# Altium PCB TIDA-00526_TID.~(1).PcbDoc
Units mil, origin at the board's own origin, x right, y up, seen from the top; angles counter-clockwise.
Board outline 2000 x 2000 mil, 2 copper layers (Top Layer, Bottom Layer), stack 62 mil thick; 38 components, 13 nets, 59 pads, 2 vias.
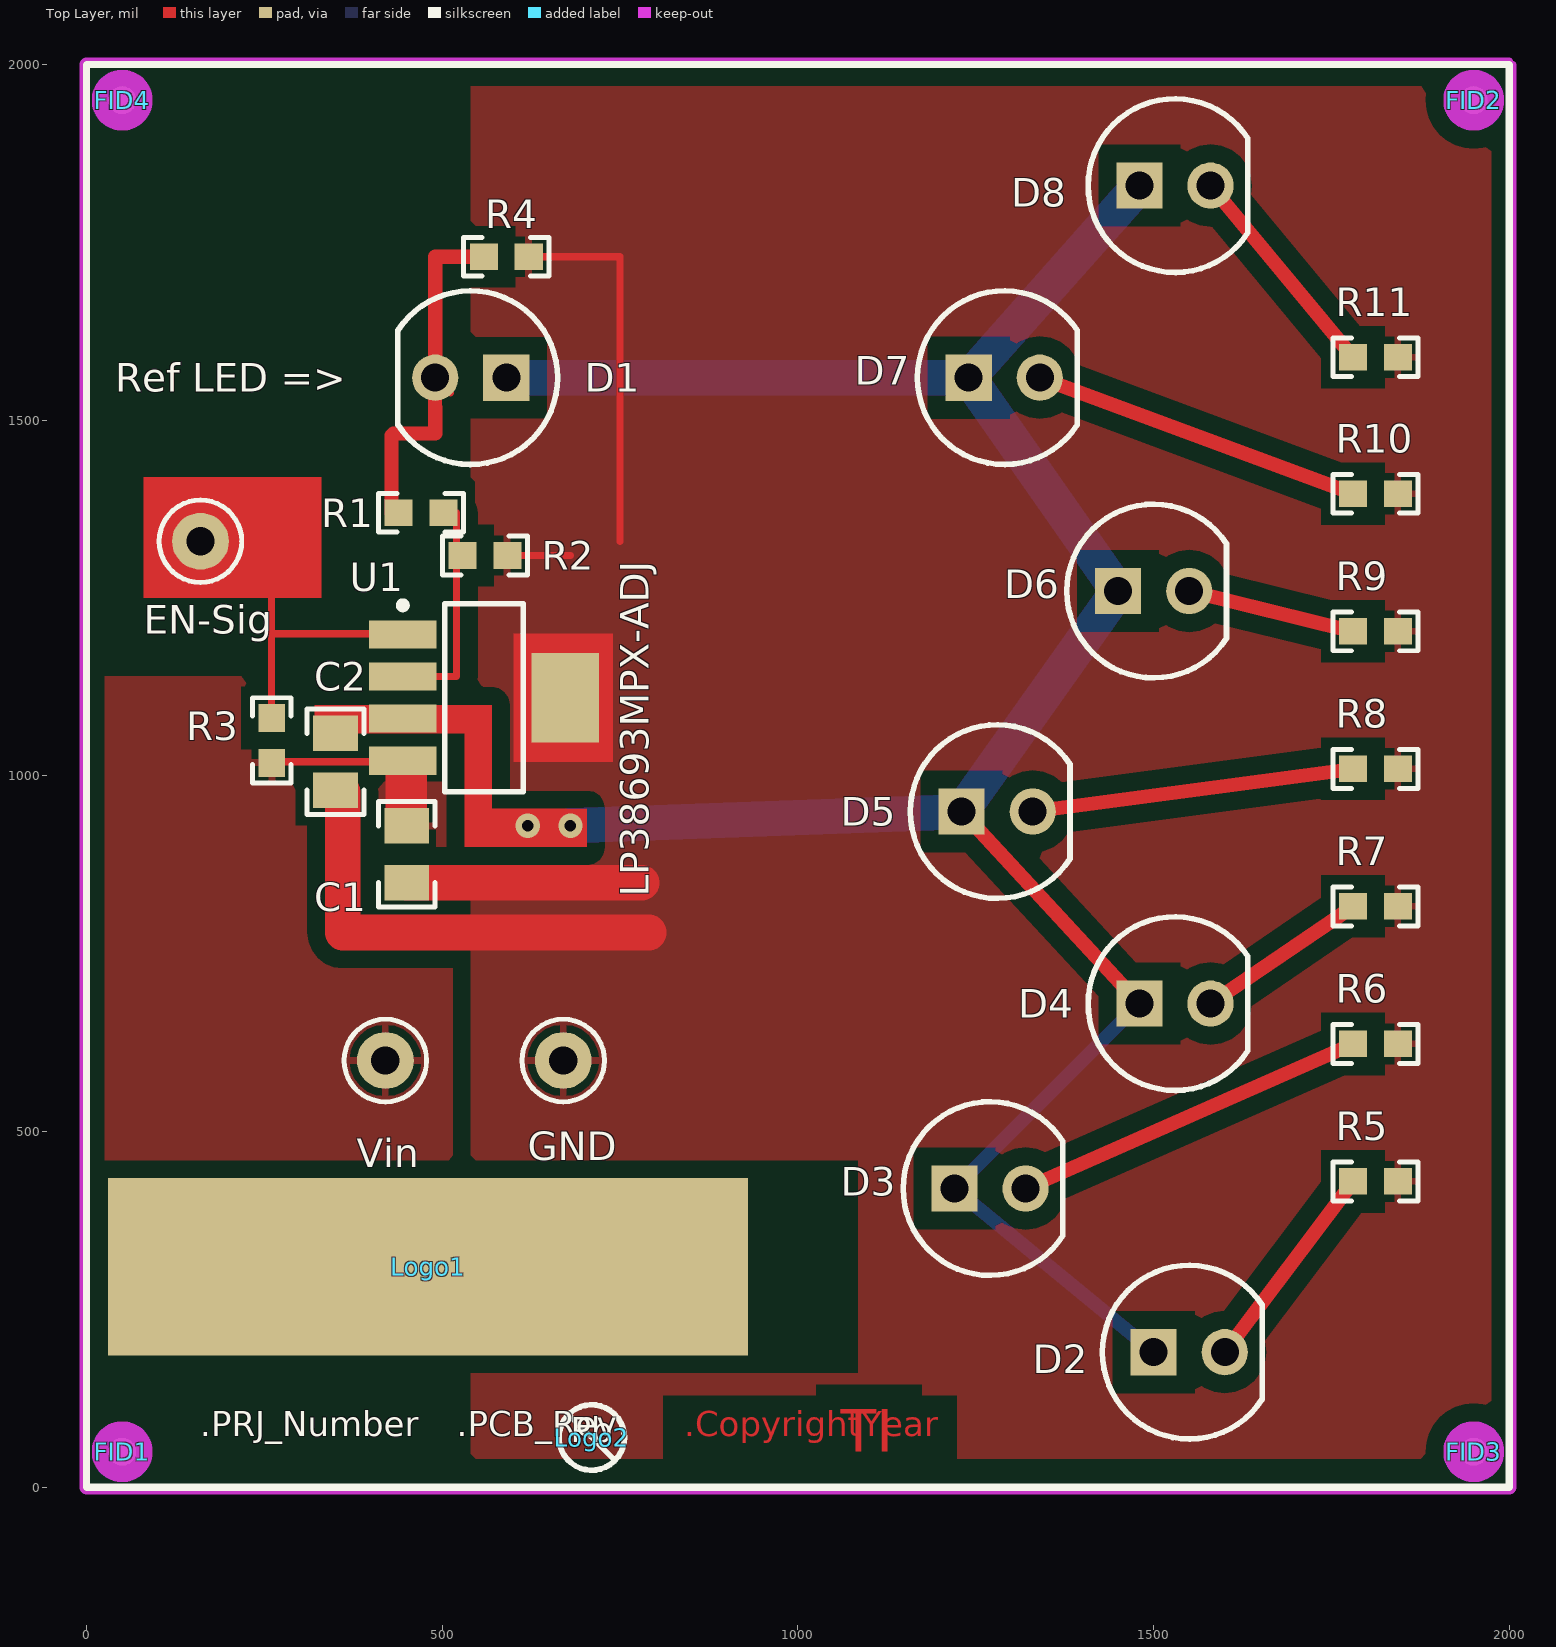
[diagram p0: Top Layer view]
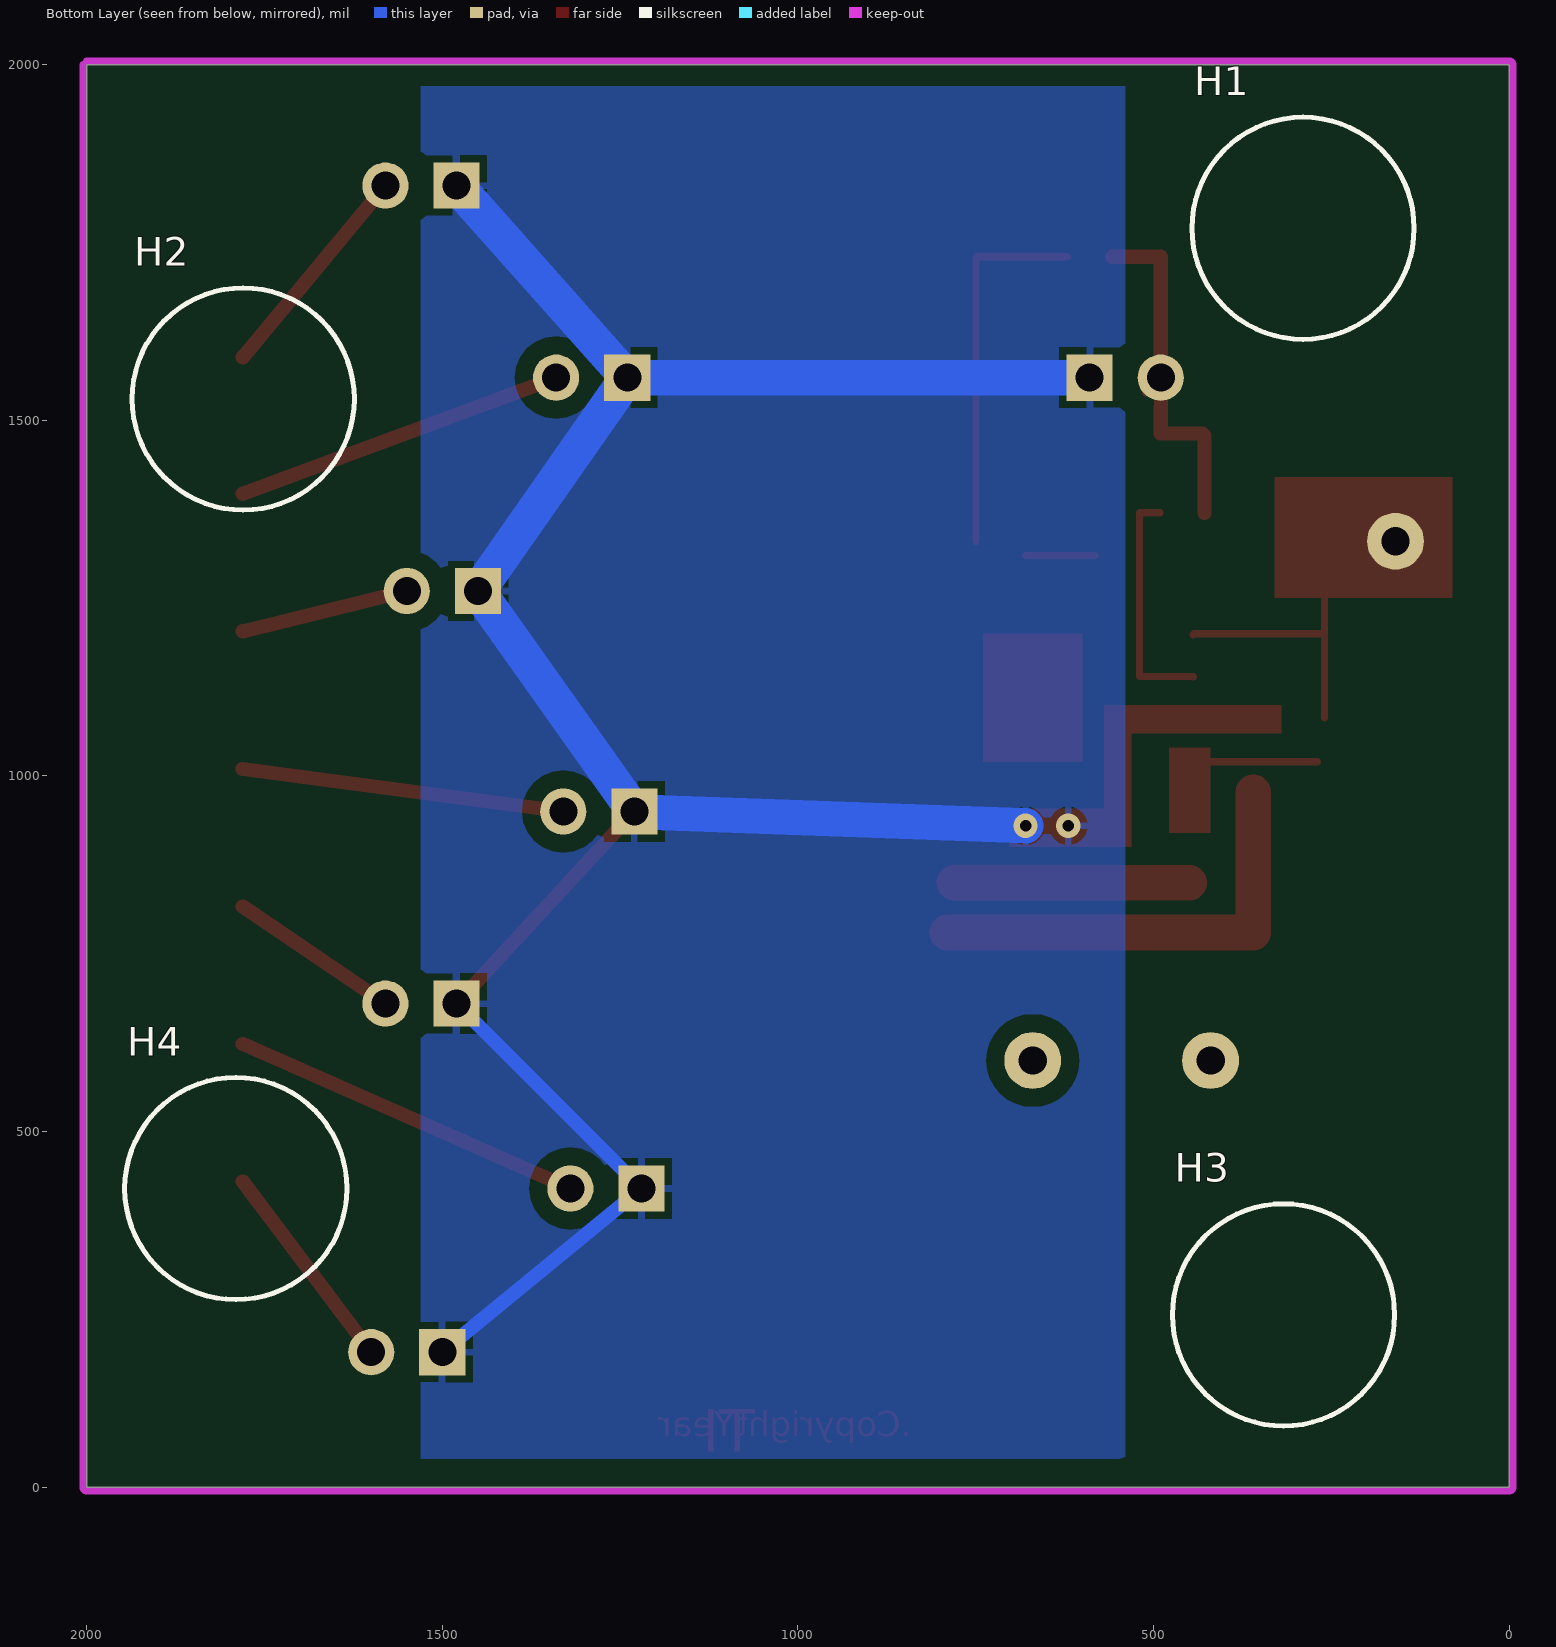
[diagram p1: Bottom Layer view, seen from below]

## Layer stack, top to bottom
Top Solder: solder mask 0.4, Solder Resist, Dk 3.5
Top Layer: signal copper 1.4
Dielectric1: core 59.2, FR-4, Dk 4.8
Bottom Layer: signal copper 1.4
Bottom Solder: solder mask 0.4, Solder Resist, Dk 3.5

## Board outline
0,0 2000,0 2000,2000 0,2000

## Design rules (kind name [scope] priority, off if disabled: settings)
AcuteAngle [All] p1: minimum=4.50000000000000E+0001 checktracksonly=FALSE
AssemblyTestPointUsage [All] p1: valid=2
Clearance Clearance_Keepouts [((IsTrack Or IsArc) And Not InPoly) And IsFree and IsKeepOut vs ((IsTrack Or IsArc) And Not InPoly) And IsFree and IsKeepOut] p1: gap=0
Clearance Clearance_BoardEdge_MountingHoles [OnCopper and InComponentClass('Mounting Holes') vs IsKeepOut] p2: gap=40
Clearance Clearance_BoardEdge_Poly [OnCopper and InPoly vs IsKeepOut] p3: gap=25
Clearance Clearance_BoardEdge [OnCopper and Not InComponentClass('Logo') and not InComponentClass('FiducialMark') and not InRegion(1000,500,4000,800) and Not IsKeepout vs IsKeepOut] p4: gap=75
Clearance Clearance_Poly [InPolygon] p5: gap=25
Clearance [All] p6: gap=7.87
ComponentClearance ComponentClearance_MountingHoles_FiducialMarks [InComponentClass('Mounting Holes') vs InComponentClass('FiducialMark')] p1: gap=50 collisioncheckmode=3 verticalgap=10 showdistances=FALSE
ComponentClearance ComponentClearance_Shunt [InComponentClass('Header') vs InComponentClass('Shunt')] p2: gap=0 collisioncheckmode=3 verticalgap=0 showdistances=FALSE
ComponentClearance ComponentClearance_Logo [InComponentClass('Logo')] p3: gap=50 collisioncheckmode=3 verticalgap=10 showdistances=FALSE
ComponentClearance ComponentClearance_ScrewToNut [(HasFootprint('NY PMS 440 0025 PH')) vs (HasFootprint('Keystone_1902C'))] p4: gap=5 collisioncheckmode=3 verticalgap=10 showdistances=FALSE
ComponentClearance ComponentClearance_MountingHoles [InComponentClass('Mounting Holes')] p5: gap=250 collisioncheckmode=3 verticalgap=100000 showdistances=FALSE
ComponentClearance ComponentClearance_SmallPassives [HasFootprint('0201*') or HasFootprint('0402*') or HasFootprint('0508') or HasFootprint('0603*') or HasFootprint('0612') or HasFootprint('0805*') or HasFootprint('0815*') or HasFootprint('0830*') or HasFootprint('1206*') or HasFootprint('1210*') or HasFootprint('1808*') or HasFootprint('1812*') or HasFootprint('1825*') or HasFootprint('2010*') or HasFootprint('2220*') or HasFootprint('2225*') or HasFootprint('2512*') or HasFootprint('2728*') or HasFootprint('3518*') vs HasFootprint('0201*') or HasFootprint('0402*') or HasFootprint('0508') or HasFootprint('0603*') or HasFootprint('0612') or HasFootprint('0805*') or HasFootprint('0815*') or HasFootprint('0830*') or HasFootprint('1206*') or HasFootprint('1210*') or HasFootprint('1808*') or HasFootprint('1812*') or HasFootprint('1825*') or HasFootprint('2010*') or HasFootprint('2220*') or HasFootprint('2225*') or HasFootprint('2512*') or HasFootprint('2728*') or HasFootprint('3518*')] p6: gap=20 collisioncheckmode=3 verticalgap=10 showdistances=FALSE
ComponentClearance ComponentClearance_THtoSMT [IsThruComponent vs IsSMTComponent] p7: gap=100 collisioncheckmode=3 verticalgap=30 showdistances=FALSE
ComponentClearance ComponentClearance_THtoTH [IsThruComponent vs IsThruComponent] p8: gap=118.11 collisioncheckmode=3 verticalgap=30 showdistances=FALSE
ComponentClearance [All] p9: gap=40 collisioncheckmode=3 verticalgap=10 showdistances=FALSE
DiffPairsRouting [All] p1: maxlimit=100 minlimit=10 mostfreqgap=10 toplayer_minwidth=15 toplayer_maxwidth=15 toplayer_prefwidth=15 bottomlayer_minwidth=15 bottomlayer_maxwidth=15 bottomlayer_prefwidth=15 maxuncoupledlength=1000
FabricationTestPointUsage TestPointUsage [All] p1: valid=2 allowmultiple=FALSE
FabricationTestpoint Testpoint [All] p1: side=3 testpointundercomponent=TRUE minsize=40 maxsize=100 preferedsize=60 minholesize=0 maxholesize=40 preferedholesize=32 testpointgrid=1 allowsidetop=TRUE allowsidebottom=TRUE usegrid=TRUE gridtolerance=0.01
FanoutControl Fanout_LCC [IsLCC] p1: bgadir=Out bgaviamode=Centered fanoutstyle=Auto fanoutdirection=Alternating viagrid=1 // Fanout_LCC (Default Rule)
FanoutControl Fanout_BGA [IsBGA] p2: bgadir=Out bgaviamode=Centered fanoutstyle=Auto fanoutdirection=Alternating viagrid=1 // Fanout_BGA (Default Rule)
FanoutControl Fanout_Default [All] p4: bgadir=Out bgaviamode=Centered fanoutstyle=Auto fanoutdirection=Alternating viagrid=1 // Fanout_Default (Default Rule)
FanoutControl Fanout_Small [(CompPinCount < 5)] p5: bgadir=Out bgaviamode=Centered fanoutstyle=Auto fanoutdirection=OutThenIn viagrid=1 // Fanout_Small (Default Rule)
HoleSize [All] p1: absolutevalues=TRUE maxlimit=251 minlimit=8 maxpercent=80.000 minpercent=20.000
MinimumAnnularRing MinimumAnnularRing_ThermalPadVias [IsVia and InAnyComponent] p1: minimumring=5.91
MinimumAnnularRing [All] p2: minimumring=9
MinimumSolderMaskSliver MinimumSolderMaskSliver_Logo [InComponentClass('Logo') vs InComponentClass('Logo')] p1: minsoldermaskwidth=0.7
MinimumSolderMaskSliver [All] p2: minsoldermaskwidth=3.94
PlaneConnect [All] p1: planeconnectstyle=Relief reliefexpansion=10 reliefentries=4 reliefconductorwidth=10 reliefairgap=10
PolygonConnect [All] p1: connectstyle=Relief reliefconductorwidth=10 reliefentries=4 polygonreliefangle="90 Angle" airgapwidth=10
RoutingVias ThermalPadVias [IsVia and InAnyComponent] p1: holewidth=7.87 width=19.68 viastyle="Through Hole" minholewidth=7.87 minwidth=19.68 maxholewidth=12.99 maxwidth=23.62
RoutingVias [All] p2: holewidth=16 width=34 viastyle="Through Hole" minholewidth=7.87 minwidth=26 maxholewidth=40 maxwidth=65
SilkToBoardRegionClearance [Not ((IsComment or IsDesignator) And (Hide <> 'False')) and not InRegion(1000,500,4000,800)] p1:
SilkToSilkClearance SilkToSilkClearance_Pb-FreeLogo [(HasFootprint('Pb-Free_Overlay_Medium') OR HasFootprint('Pb-Free_Overlay_Small')) vs (HasFootprint('Pb-Free_Overlay_Medium') OR HasFootprint('Pb-Free_Overlay_Small'))] p1: silktosilkclearance=0
SilkToSilkClearance [All] p2: silktosilkclearance=5
SilkToSolderMaskClearance "Silk to Solder Mask Opening" [All] p1: minsilkscreentomaskgap=1 clearancetoexposedcopper=FALSE
SolderMaskExpansion [All] p1: expansion=1.97
UnpouredPolygon [All] p1: allowunpoured=FALSE
Width [All] p1: maxlimit=100 minlimit=6 preferedwidth=10 checkconnectedcopper=TRUE
14 further rules are at their usual default settings.

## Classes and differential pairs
component class Logo: Logo1
component class TIDA-00526_Hardware: FID1 FID2 FID3 FID4 H1 H2 H3 H4 Logo1 Logo2 ZZ2 ZZ3 ZZ4
component class FiducialMark: FID1 FID2 FID3 FID4
component class AssemblyNote: ZZ2 ZZ3 ZZ4
component class TIDA-00526_BlankSheet: C1 C2 D1 D2 D3 D4 D5 D6 D7 D8 D? EN-Sig GND R1 R2 R3 R4 R5 R6 R7 R8 R9 R10 R11 U1 Vin

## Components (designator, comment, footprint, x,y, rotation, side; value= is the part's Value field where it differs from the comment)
C1 "C0805C104K3RACTU" 0805_HV 450,890 r90 top
C2 "C0805C104K3RACTU" 0805_HV 350,1020 r90 top
D1 "C503D-WAN-CCBDB232" HLMP-341_YELLOW 540,1560 r180 top
D2 "C503D-WAN-CCBDB232" HLMP-341_YELLOW 1550,190 r0 top
D3 "LED, White, TH" HLMP-341_YELLOW 1270,420 r0 top
D4 "C503D-WAN-CCBDB232" HLMP-341_YELLOW 1530,680 r0 top
D5 "C503D-WAN-CCBDB232" HLMP-341_YELLOW 1280,950 r0 top
D6 "C503D-WAN-CCBDB232" HLMP-341_YELLOW 1500,1260 r0 top
D7 "C503D-WAN-CCBDB232" HLMP-341_YELLOW 1290,1560 r0 top
D8 "C503D-WAN-CCBDB232" HLMP-341_YELLOW 1530,1830 r0 top
EN-Sig "5002" Keystone5002 160,1330 r0 top
FID1 "Fiducial" Fiducial10-20 50,50 r0 top
FID2 "Fiducial" Fiducial10-20 1950,1950 r0 top
FID3 "Fiducial" Fiducial10-20 1950,50 r0 top
FID4 "Fiducial" Fiducial10-20 50,1950 r0 top
GND "5001" Keystone5001 670,600 r0 top
H1 "SJ61A1" Bumpon_SJ61A1 290,1770 r180 bottom
H2 "SJ61A1" Bumpon_SJ61A1 1780,1530 r180 bottom
H3 "SJ61A1" Bumpon_SJ61A1 317.38,242.36 r180 bottom
H4 "SJ61A1" Bumpon_SJ61A1 1790.3,420 r180 bottom
Logo1 "Texas Instruments" TI_Stacked_SolderMask_Small 480,310 r0 top
Logo2 "Pb-Free Symbol" Pb-Free_Overlay_Small 710,70 r0 top
R1 "CRCW06032K32FKEA" 0603 470,1370 r180 top
R2 "RC0603FR-0712KL" 0603 560,1310 r180 top
R3 "CRCW060310K0FKEA" 0603 260,1050 r270 top
R4 "CRCW0603102RFKEA" 0603 590,1730 r180 top
R5 "CRCW0603102RFKEA" 0603 1811.95,430 r180 top
R6 "CRCW0603102RFKEA" 0603 1811.95,623.33 r180 top
R7 "CRCW0603102RFKEA" 0603 1811.95,816.67 r180 top
R8 "CRCW0603102RFKEA" 0603 1811.95,1010 r180 top
R9 "CRCW0603102RFKEA" 0603 1811.95,1203.33 r180 top
R10 "CRCW0603102RFKEA" 0603 1811.95,1396.67 r180 top
R11 "CRCW0603102RFKEA" 0603 1811.95,1588.7 r180 top
U1 "LP38693MP-ADJ" MP05A_N 558.54,1110 r0 top
Vin "5000" Keystone5000 420,600 r0 top (schematic designator VCC)
ZZ2 "These assemblies are ESD sensitive, ESD precautions shall be observed." AssemblyNote 185,3829.11 r0 top
ZZ3 "These assemblies must be clean and free from flux and all contaminants. Use of no clean flux is not acceptable." AssemblyNote 185,3740.56 r0 top
ZZ4 "These assemblies must comply with workmanship standards IPC-A-610 Class 2, unless otherwise specified." AssemblyNote 185,3652 r0 top

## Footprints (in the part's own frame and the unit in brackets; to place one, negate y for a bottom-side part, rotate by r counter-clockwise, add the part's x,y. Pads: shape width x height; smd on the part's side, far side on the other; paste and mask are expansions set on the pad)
0603 [mm] "0603 from SM-752 data"
  rect 1x0.95 smd: 1(-0.8,0) 2(0.8,0)
  silkscreen extent -1.52,-0.69 1.52,0.69, body extent -0.87,-0.47 0.87,0.47, height 0.85
0805_HV [mil] "0805 with 30mil clearance between pads"
  rect 50x63 smd: 1(-40,0) 2(40,0)
  silkscreen extent -74,-40 74,40, body extent -43,-29 43,29, height 43
AssemblyNote [mil] "Assembly Note"
Bumpon_SJ61A1 [mil] "3M Cylindrical Bumpon black"
  round 1 on Mech4: 0(0,0)
  silkscreen extent -156,-156 156,156, body extent -156,-155 156,156, height 201
Fiducial10-20 [mm]
  round 1 smd mask+0.5: 1(0,0)
  Top Layer keep-out circle w1.178: c0,0 r0.5
HLMP-341_YELLOW [mm] "AVAGO"
  rect 1.65x1.65 hole 1: 1(-1.27,0)
  round 1.65 hole 1: 2(1.27,0)
  silkscreen extent -3.1,-3.1 2.6,3.1, body extent -3.06,-3.06 2.58,3.06, height 10.78
Keystone5000 [mil] "For Keystone 500x miniature loop terminals"
  round 80 hole 40: 1(0,0)
  silkscreen extent -58,-58 58,58, body extent -49,-49 49,49, height 182
Keystone5001 [mil] "For Keystone 500x miniature loop terminals"
  round 80 hole 40: 1(0,0)
  silkscreen extent -58,-58 58,58, body extent -49,-49 49,49, height 182
Keystone5002 [mil] "For Keystone 500x miniature loop terminals"
  round 80 hole 40: 1(0,0)
  silkscreen extent -58,-58 58,58, body extent -49,-49 49,49, height 182
MP05A_N [mm] "SOT223, 5-Leads, Body 6.5x3.5mm, Pitch 1.5mm, Lead Span 7mm, IPC Medium Density"
  rect 2.4x1 smd: 1(-2.9,2.25) 2(-2.9,0.75) 3(-2.9,-0.75) 4(-2.9,-2.25)
  rect 2.4x3.2 smd: 5(2.9,0)
  silkscreen extent -3.02,-3.35 1.4,3.42, body extent -1.85,-3.35 1.85,3.35, height 1.8
Pb-Free_Overlay_Small [mil]
  silkscreen extent -46,-46 46,46
TI_Stacked_SolderMask_Small [mil]
  rect 900x250 smd paste-125 mask-125: 0(0,0)

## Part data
C1 C2: "CAP, CERM, 0.1 µF, 25 V, +/- 10%, X7R, 0805"
D1 D2 D4 D5 D7 D8: library part HLMP-3416, "LED, White, TH"
D3: library part HLMP-3416
D6: library part HLMP-3416, "LED, white, TH"
EN-Sig: "Test Point, Miniature, White, TH"
FID1 FID2 FID3 FID4: "Fiducial mark.  There is nothing to buy or mount."
GND: "Test Point, Miniature, Black, TH"
H1 H2 H3 H4: "Bumpon, Cylindrical, 0.312 X 0.200, Black"
Logo1: library part TI_Logo, "Texas Instrument Corporate Signature"
Logo2: library part Pb-Free
R1: "RES, 2.32 k, 1%, 0.1 W, 0603"
R2: "RES, 12.0 k, 1%, 0.1 W, 0603"
R3: "RES, 10.0 k, 1%, 0.1 W, 0603"
R4 R5 R6 R7 R8 R9 R10 R11: "RES, 102, 1%, 0.1 W, 0603"
U1: "500mA Low Dropout CMOS Linear Regulators, 5-pin SOT-223"
Vin: "Test Point, Miniature, Red, TH"
ZZ2 ZZ3 ZZ4: library part AssemblyNote

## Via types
v1: diameter 34, hole 16, Top Layer to Bottom Layer, 2 vias

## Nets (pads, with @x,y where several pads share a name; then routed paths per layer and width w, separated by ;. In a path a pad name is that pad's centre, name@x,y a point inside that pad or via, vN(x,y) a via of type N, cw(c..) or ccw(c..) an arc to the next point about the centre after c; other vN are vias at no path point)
GND: C1.1 C2.1 GND.1 R2.1 R4.1 R5.1 R6.1 R7.1 R8.1 R9.1 R10.1 R11.1 U1.5 | length 1588.3
  Top Layer w10: C2.1 C2.1@353.05,976.95 ; R2.1@581.5,1310 680,1310 ; R4.1 750,1730 750,1330
  Top Layer w50: C2.1@360,976.95 360,780 790,780 ; C1.1 780,850
NetC1_2: C1.2 R3.2 U1.4 Vin.1 | length 173
  Top Layer w10: R3.2@270,1020 U1.4@442.95,1020
NetD1_2: D1.2 R1.2 R4.2 | length 510.4
  Top Layer w10: D1.2@510,1540 D1.2@511.5,1538.5
  Top Layer w20: R1.2@428.5,1370 428.5,1478.5 431.5,1481.5 490,1481.5 D1.2@489.8,1560 ; D1.2@490,1540 490,1730 R4.2
NetD2_2: D2.2 R5.2 | length 300.3
  Top Layer w20: D2.2 R5.2
NetD3_2: D3.2 R6.2 | length 503.4
  Top Layer w20: D3.2 R6.2
NetD4_2: D4.2 R7.2 | length 242.6
  Top Layer w20: D4.2 R7.2
NetD5_2: D5.2 R8.2 | length 454.4
  Top Layer w20: D5.2 R8.2
NetD6_2: D6.2 R9.2 | length 237.3
  Top Layer w20: D6.2 R9.2
NetD7_2: D7.2 R10.2 | length 469.8
  Top Layer w20: D7.2 R10.2
NetD8_2: D8.2 R11.2 | length 313.7
  Top Layer w20: D8.2 R11.2
NetEN-Sig_1: EN-Sig.1 R3.1 U1.1 | length 520.4
  Top Layer w10: EN-Sig.1 221.5,1268.5 ; R3.1 260,1200 ; 260,1330 260,1200 ; U1.1 442.95,1200 260,1200
NetR1_1: R1.1 R2.2 U1.2 | length 334.1
  Top Layer w10: U1.2 520,1140 520,1370 R1.1 R1.1@491.5,1370
VOUT: C2.2 D1.1 D2.1 D3.1 D4.1 D5.1 D6.1 D7.1 D8.1 U1.3 | length 3464.2
  Top Layer w10: 650,930 v1(680,930)
  Top Layer w20: D5.1 D4.1
  Bottom Layer w10: D5.1@1210,930 D5.1
  Bottom Layer w20: D4.1 D3.1 D2.1
  Bottom Layer w50: D1.1 D7.1 ; v1(680,930) D5.1 D6.1 D7.1 ; D8.1 D7.1
  other v1: 620,930
pads on no net: FID1.1 FID2.1 FID3.1 FID4.1 H1.0 H2.0 H3.0 H4.0 Logo1.0

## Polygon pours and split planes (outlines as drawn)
NetC1_2 on Top Layer "Top Layer-No Net 2" (solid, remove dead copper, pour order 9): 20,1140 600,1140 600,400 20,400
GND on Top Layer "Top Layer-No Net 1" (solid, remove dead copper, pour order 7): 540,1970 540,40 1980,40 1980,1970
VOUT on Top Layer "Top Layer-No Net" (solid, remove dead copper, shelved, pour order 2): 0,0 0,2000 2000,2000 2000,0
VOUT on Bottom Layer "Bottom Layer-No Net" (solid, remove dead copper, pour order 12): 540,1970 1530,1970 1530,40 550,40 540,30

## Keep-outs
Keep-Out Layer:
  lines w10: 2000,2005 0,2005 ccw(c0,2000) -5,2000 -5,0 ccw(c0,0) 0,-5 2000,-5 ccw(c2000,0) 2005,0 2005,2000 ; 4950,-5 ccw(c4950,0) 4955,0 cw(c4950,0) 4950,-5 ; 4950,3455 cw(c4950,3450) 4955,3450 ccw(c4950,3450) 4950,3455
  text ".Layer_Name" at 577,-858.49 h60

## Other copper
Top Layer:
  rectangle net GND: 600,1020 740,1200
  rectangle net NetEN-Sig_1: 80,1250 330,1420
  rectangle net VOUT: 531.3,900 570,1088.35
  rectangle net VOUT: 418.54,1060 570,1100
  rectangle net VOUT: 560,900 703.65,954.02
  rectangle net VOUT: 320,1060 418.54,1100
  rectangle net NetC1_2: 420,920 478.54,1040
  text ".CopyrightYear" at 840,60 h60
  text "TI" at 1060,50 h60
  text ".Layer_Name" at 577,-858.49 h60
Bottom Layer:
  text ".Layer_Name" at 577,-858.49 h60

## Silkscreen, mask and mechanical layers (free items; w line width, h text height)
Top Overlay:
  the board outline again, w10
  text "Ref LED =>" at 40,1540 h40
  text "LP38693MPX-ADJ" at 790,830 h40 r90
  text ".PRJ_Number" at 160,60 h60
  text ".PCB_Rev" at 520,60 h60
  text ".Layer_Name" at 577,-858.49 h60
Bottom Overlay:
  text ".Layer_Name" at 577,-858.49 h60
Top Paste:
  text ".Layer_Name" at 577,-858.49 h60
Bottom Paste:
  text ".Layer_Name" at 577,-858.49 h60
Top Solder:
  the board outline again, w10
  text ".Layer_Name" at 577,-858.49 h60
  text ".Layer_Name" at 577,-858.49 h60
Bottom Solder:
  lines w10: 0,0 2000,0 ; 0,0 0,2000 ; 0,0 2000,0 ; 0,0 0,2000 ; 0,2000 2000,2000 ; 0,2000 2000,2000 ; 2000,0 2000,2000 ; 2000,0 2000,2000
  text ".Layer_Name" at 577,-858.49 h60
Drill Guide:
  text ".Layer_Name" at 577,-858.49 h60
M1 Board Outline:
  the board outline again, w10
  text ".Layer_Name" at 577,-858.49 h60
M2 Board Dimensions:
  rectangle: 0,-275 125,-150
  rectangle: 125,-400 500,-275
  lines w7: 0,-275 1000,-275 ; 125,-400 125,-150 ; 250,-400 250,-150 ; 500,-400 500,-150 ; 750,-400 750,-150 ; 0,-400 1000,-400 1000,-150 0,-150 0,-400
  text ".Layer_Name" at 577,-858.49 h60
M3 3D STEP Top:
  text ".Layer_Name" at 577,-858.49 h60
M4 3D STEP Bottom:
  text ".Layer_Name" at 577,-858.49 h60
M5 Assembly Top:
  lines w10: -292,-930.17 6308,-930.17 ; -292,-726.83 6310,-726.83 ; -292,-523.5 -292,-1133.5 3713,-1133.5 6310,-1133.5 6310,-523.5 -291.5,-523.5 -291.5,-1133.5 1284,-1133.5 ; 2173,-1133.5 2173,-523.5 ; 3440,-726.83 3440,-523.5 ; 4280,-726.83 4280,-523.5 ; 4902,-1140 4902,-937.17
  text "COMPONENTS MARKED 'DNP' SHOULD NOT BE POPULATED." at 1153.5,-318.5 h60
  text "ASSEMBLY VARIANT:" at 1153,-434 h60
  text ".VariantName" at 2189,-434 h60
  text "PCB VIEWED FROM TOP SIDE" at -228.5,-655.67 h60
  text "BOARD #:" at 2248,-655.67 h60
  text ".PRJ_Number" at 2793.5,-655.67 h60
  text "REV:" at 3638,-655.67 h60
  text ".PCB_Rev" at 3929.5,-655.67 h60
  text "SVN REV:" at 4476,-655.67 h60
  text ".VersionControl_RevNumber" at 4982,-655.67 h60
  text "PLOT NAME =" at -228.5,-1064.34 h60
  text ".plot_File_Name" at 577,-1064.34 h60
  text "GENERATED    :" at 2250,-1064.34 h60
  text ".Print_Date" at 3119.5,-1064.34 h60
  text ".Print_Time" at 3848.5,-1064.34 h60
  text "TEXAS INSTRUMENTS" at 5113,-1064.34 h60
M6 Assembly Bottom:
  lines w10: -292.5,-727.33 6309.5,-727.33 ; -290.5,-930.67 6309.5,-930.67 ; 1115.5,-1140.5 1115.5,-937.67 ; 1737.5,-727.33 1737.5,-524 ; 2577.5,-727.33 2577.5,-524 ; 3844.5,-1134 3844.5,-524 ; 4733.5,-1134 6309,-1134 6309,-524 -292.5,-524 -292.5,-1134 2304.5,-1134 6309.5,-1134 6309.5,-524
  text "COMPONENTS MARKED 'DNP' SHOULD NOT BE POPULATED." at 6102,-318 h60
  text ".VariantName" at 5058,-434 h60
  text "ASSEMBLY VARIANT:" at 6097,-434 h60
  text ".VersionControl_RevNumber" at 1035.5,-656.17 h60
  text "SVN REV:" at 1541.5,-656.17 h60
  text ".PCB_Rev" at 2088,-656.17 h60
  text "REV:" at 2379.5,-656.17 h60
  text ".PRJ_Number" at 3224,-656.17 h60
  text "BOARD #:" at 3769.5,-656.17 h60
  text "PCB VIEWED FROM BOTTOM SIDE" at 6246,-656.17 h60
  text "TEXAS INSTRUMENTS" at 904.5,-1064.84 h60
  text ".Print_Time" at 2169,-1064.84 h60
  text ".Print_Date" at 2898,-1064.84 h60
  text "GENERATED    :" at 3767.5,-1064.84 h60
  text ".plot_File_Name" at 5440.5,-1064.84 h60
  text "PLOT NAME =" at 6246,-1064.84 h60
M9 Title Sheet:
  drawing of 57 lines, arcs and shapes, not listed
  text "1" at 739.84,8036.5 h70
  text "2" at 3235.5,8036.5 h70
  text "3" at 5724.84,8036.5 h70
  text "4" at 8231.51,8036.5 h70
  text "5" at 10730.5,8036.5 h70
  text "6" at 13235.5,8036.5 h70
  text "A" at -416.5,6893.5 h70
  text "A" at 14383.5,6893.5 h70
  text "B" at -416.5,4513.5 h70
  text "B" at 14383.5,4513.5 h70
  text "C" at -416.5,2138.5 h70
  text "C" at 14383.5,2138.5 h70
  text "PROJECT TITLE:" at 11343.5,277.5 h45
  text ".PRJ_Title" at 11393.5,144.17 h70
  text "DESIGNED FOR:" at 11343.5,-23.5 h45
  text ".PRJ_Customer" at 11393.5,-163.5 h70
  text "D" at -416.5,-231.5 h70
  text "D" at 14383.5,-231.5 h70
  text "FILE NAME:" at 11343.5,-323.5 h45
  text ".PCB_File_Name_No_Path" at 11393.5,-443.5 h70
  text "Texas Instruments (TI) and/or its licensors do not warrant the accuracy or completeness of this specification" at 6374,-605.34 h45
  text "ENGINEER:" at 11343.5,-613.5 h45
  text "LAYOUT BY:" at 12848.5,-613.5 h45
  text "or any information contained therein. TI and/or its licensors do not warrant that this design will meet" at 6329.01,-718 h45
  text ".PRJ_Engineer" at 11393.5,-768.49 h70
  text ".PCB_Layout" at 12899,-768.49 h70
  text "the specifications, will be suitable for your application or fit for any particular purpose, or will operate in" at 6329.01,-830.67 h45
  text ".Layer_Name" at 577,-858.49 h60
  text "ALTIUM DESIGNER VERSION:" at 12848.5,-923.5 h45
  text "an implementation. TI and/or its licensors do not warrant that the design is production worthy. You should" at 6329.01,-943.33 h45
  text "completely validate and test your design implementation to confirm the system functionality for your application." at 6374,-1056 h45
  text ".print_Scale" at 11393.5,-1056.83 h70
  text ".Application_BuildNumber" at 12899,-1056.83 h70
  text "1" at 739.84,-1263.5 h70
  text "2" at 3235.5,-1263.5 h70
  text "3" at 5724.84,-1263.5 h70
  text "4" at 8231.51,-1263.5 h70
  text "5" at 10730.5,-1263.5 h70
  text "6" at 13235.5,-1263.5 h70
M10 Fab Notes:
  drawing of 185 lines, arcs and shapes, not listed
  text "DESIGN INFORMATION" at 12381.02,5910 h60
  text "MIN. TRACK WIDTH:" at 11736.46,5730 h60
  text "8" at 12832.7,5730 h60
  text "MIL" at 12987.46,5730 h60
  text "MIN. CLEARANCE:" at 11736.46,5598 h60
  text "0.2" at 12772.7,5598 h60
  text "mm" at 12987.46,5598 h60
  text "MIN. VIA PAD SIZE:" at 11736.46,5466 h60
  text "24" at 12802.71,5466 h60
  text "MIL" at 12987.46,5466 h60
  text "0.05mm (2MIL)" at 12431.46,5324.29 h60
  text "MINIMUM ANNULAR RING" at 11407.23,5320 h60
  text "EXTERNAL" at 13139.46,5320 h60
  text "PER" at 11607.23,5202 h60
  text "IPC-D-275 CLASS 2 LEVEL C" at 11827.23,5202 h60
  text "MIL, HOLES" at 13315.46,5089.71 h60
  text "+/-" at 12923,5089 h60
  text "+/-" at 13777,5089 h60
  text "REGISTRATION TOLERANCES:" at 11407.23,5084 h60
  text "METAL" at 12607,5084 h60
  text "5" at 13183.2,5084 h60
  text "3" at 14016.2,5084 h60
  text "MIL" at 14132.46,5084 h60
  text "MATERIAL:" at 11332.46,4874.54 h60
  text "FR-4 High Tg" at 12318.9,4734.21 h60
  text "FR-408" at 11753.46,4725.64 h60
  text "X" at 12165.46,4725.64 h60
  text "OTHER" at 13241.46,4725.64 h60
  text "62 MIL (1.6mm) +/-10%" at 12073.56,4562.92 h60
  text "THICKNESS:" at 11407.23,4558.64 h60
  text "X" at 11945.4,4558.64 h60
  text "OTHER" at 13358.46,4558.64 h60
  text "TOLERANCE:" at 11407.23,4400.64 h60
  text "X" at 12246.53,4400.64 h60
  text "ANSI IPC-6012 TYPE 3 CLASS 2" at 12433.48,4400.64 h60
  text "OTHER +/-" at 12433.46,4244.64 h60
  text "BOW & TWIST:" at 11407.23,4087.64 h60
  text "X" at 12246.53,4087.64 h60
  text "ANSI IPC-6012 TYPE 3 CLASS 2" at 12433.48,4087.64 h60
  text "OTHER +/-" at 12433.46,3929.13 h60
  text "DRILLING:" at 11332.46,3790.64 h60
  text "REFERENCE:" at 11407.23,3673.64 h60
  text "X" at 12055.46,3673.64 h60
  text "AS SHOWN" at 12242.46,3673.64 h60
  text "X" at 12956.46,3673.64 h60
  text "NC_DRILL FILES" at 13093.46,3673.64 h60
  text "PTH MIN COPPER THICKNESS:" at 11407.23,3515.64 h60
  text "X" at 12757.46,3515.64 h60
  text "1MIL" at 12894.46,3515.64 h60
  text "OTHER" at 13391.46,3515.64 h60
  text "BOARD FINISH:" at 11332.46,3356.64 h60
  text "SILKSCREEN:" at 11487.68,3238.64 h60
  text "X" at 12436.46,3238.64 h60
  text "TOP" at 12562.46,3238.64 h60
  text "X" at 12946.46,3238.64 h60
  text "BOTTOM" at 13073.46,3238.64 h60
  text "SILKSCREEN COLOR:" at 11487.68,3071.64 h60
  text "X" at 12435.42,3071.64 h60
  text "WHITE" at 12562.46,3071.64 h60
  text "OTHER" at 13073.46,3071.64 h60
  text "SOLDER RESIST COLOR:" at 11487.68,2901.64 h60
  text "X" at 12055.42,2742.44 h60
  text "GREEN" at 12182.46,2742.44 h60
  text "BLUE" at 12773.46,2742.44 h60
  text "OTHER" at 13311.46,2742.44 h60
  text "IMMERSION GOLD (ENIG)" at 12393.46,2553.92 h60
  text "ENEPIG" at 13731,2550.64 h60
  text "SURFACE FINISH:" at 11332.46,2549.64 h60
  text "X" at 12206.51,2549.64 h60
  text "IMM. TIN/SILVER OR EQUIV" at 11662,2392.64 h60
  text "OTHER" at 13093.46,2392.64 h60
  text "ARRAY/PANEL:" at 11332.46,2213.64 h60
  text "CUT AND TRIM PER MECH LAYER 1" at 12393.46,2209.35 h60
  text "N.C. ROUTE" at 12393.46,2057.64 h60
  text "X" at 13072.46,2057.64 h60
  text "V. SCORE" at 13259.46,2057.64 h60
  text "CERTIFICATION:" at 11332.46,1920.64 h60
  text "MATERIALS AND WORKMANSHIP FOR ALL PCBS" at 12057.46,1920.64 h60
  text "TO MEET OR EXCEED THE REQUIREMENTS OF:" at 12057.46,1822.64 h60
  text "X" at 11683.96,1686.13 h60
  text "ANSI IPC-A-600F CLASS ->" at 11822.96,1686.13 h60
  text "X" at 13462.02,1686.13 h60
  text "2" at 13580.96,1686.14 h60
  text "1" at 13265.96,1684.64 h60
  text "3" at 13934.96,1684.64 h60
  text "X" at 11686.02,1526.64 h60
  text "UL 94V-0" at 11822.96,1526.64 h60
  text "X" at 12498.02,1526.64 h60
  text "RoHS" at 12634.96,1526.64 h60
  text "OTHER" at 13279.36,1526.64 h60
  text "PER ORDER" at 13676.42,1526.64 h60
  text "ADDITIONAL REQUIREMENTS:" at 11332.46,1385.64 h60
  text "MICROSECTION:" at 11407.23,1270.64 h60
  text "YES" at 12312.96,1270.64 h60
  text "REQUIRED" at 13174.46,1114.49 h60
  text "BARE BOARD ELEC. TEST:" at 11407.23,1111.64 h60
  text "NONE" at 12712.96,1111.64 h60
  text "X" at 13047.46,1111.64 h60
  text "PER ORDER" at 13766.46,1111.64 h60
  text "MANUFACTURER'S UL:" at 11407.23,954.64 h60
  text "RAIL" at 12572.96,950.35 h60
  text "METAL" at 13064.77,950.35 h60
  text "X" at 13440,950 h60
  text "SILK" at 13576.46,950.35 h60
  text ".Layer_Name" at 577,-858.49 h60
M11 Gerber Information:
  lines w10: -292,-930.17 6308,-930.17 ; -292,-726.83 6310,-726.83 ; -292,-523.5 -292,-1133.5 3713,-1133.5 6310,-1133.5 6310,-523.5 -291.5,-523.5 -291.5,-1133.5 1284,-1133.5 ; 2173,-1133.5 2173,-523.5 ; 3440,-726.83 3440,-523.5 ; 4280,-726.83 4280,-523.5 ; 4902,-1140 4902,-937.17
  text "ALL ARTWORK VIEWED FROM TOP SIDE" at -228.5,-655.67 h60
  text "BOARD #:" at 2248,-655.67 h60
  text ".PRJ_Number" at 2793.5,-655.67 h60
  text "REV:" at 3638,-655.67 h60
  text ".PCB_Rev" at 3929.5,-655.67 h60
  text "SVN REV:" at 4476,-655.67 h60
  text ".VersionControl_RevNumber" at 4982,-655.67 h60
  text "LAYER NAME =" at -228.5,-858.49 h60
  text "PLOT NAME =" at -228.5,-1064.34 h60
  text ".plot_File_Name" at 577,-1064.34 h60
  text "GENERATED    :" at 2250,-1064.34 h60
  text ".Print_Date" at 3119.5,-1064.34 h60
  text ".Print_Time" at 3848.5,-1064.34 h60
  text "TEXAS INSTRUMENTS" at 5113,-1064.34 h60
M12 Stackup:
  drawing of 191 lines, arcs and shapes, not listed
  text "Layer" at 9790.58,7830 h60
  text "Name" at 10200.49,7830 h60
  text "Material" at 11130.23,7830 h60
  text "Thickness" at 11990,7830 h60
  text "Constant" at 12639.84,7830 h60
  text "Board Layer Stack" at 13209.7,7830 h60
  text "1" at 9790.58,7710 h60
  text "Top Overlay" at 10200.49,7710 h60
  text "2" at 9790.58,7590 h60
  text "Top Solder" at 10200.49,7590 h60
  text "Solder Resist" at 11130.23,7590 h60
  text "0.40mil" at 11990,7590 h60
  text "3.5" at 12639.84,7590 h60
  text "3" at 9790.58,7470 h60
  text "Top Layer" at 10200.49,7470 h60
  text "Copper" at 11130.23,7470 h60
  text "1.40mil" at 11990,7470 h60
  text "4" at 9790.58,7350 h60
  text "Dielectric1" at 10200.49,7350 h60
  text "FR-4" at 11130.23,7350 h60
  text "59.20mil" at 11990,7350 h60
  text "4.8" at 12639.84,7350 h60
  text "5" at 9790.58,7230 h60
  text "Bottom Layer" at 10200.49,7230 h60
  text "Copper" at 11130.23,7230 h60
  text "1.40mil" at 11990,7230 h60
  text "6" at 9790.58,7110 h60
  text "Bottom Solder" at 10200.49,7110 h60
  text "Solder Resist" at 11130.23,7110 h60
  text "0.40mil" at 11990,7110 h60
  text "3.5" at 12639.84,7110 h60
  text "7" at 9790.58,6990 h60
  text "Bottom Overlay" at 10200.49,6990 h60
  text ".Layer_Name" at 577,-858.49 h60
M13 Component Bodies Top:
  text ".Layer_Name" at 577,-858.49 h60
M14 Component Bodies Bottom:
  text ".Layer_Name" at 577,-858.49 h60
M15 Courtyards Top:
  text ".Layer_Name" at 577,-858.49 h60
M16 Courtyards Bottom:
  text ".Layer_Name" at 577,-858.49 h60
Drill Drawing:
  circle w1: c5572.73,3071.68 r24.89
  lines w1: 5547.84,2947.24 5597.62,2947.24 5572.73,2897.46 5547.84,2947.24 ; 5547.84,3196.13 5597.62,3196.13 5597.62,3245.91 5547.84,3245.91 5547.84,3196.13
  lines w12: 5480,2852.66 7596.94,2852.66 ; 5480,3300.66 7596.94,3300.66 ; 5850.25,2703.32 5850.25,3450 ; 6207.06,2703.32 6207.06,3450 ; 6868.16,2703.32 6868.16,3450 ; 7152.16,2703.32 7152.16,3450 ; 5480,2703.32 7596.94,2703.32 7596.94,3450 5480,3450 5480,2703.32
  text "Symbol" at 5569.6,3345.47 h72
  text "Quantity" at 5895.05,3345.47 h72
  text "Finished Hole Size" at 6251.86,3345.47 h72
  text "Plated" at 6912.96,3345.47 h72
  text "Hole Type" at 7196.96,3345.47 h72
  text "2" at 5895.05,3196.13 h60
  text "16.00mil (0.406mm)" at 6251.86,3196.13 h60
  text "PTH" at 6912.96,3196.13 h60
  text "Round" at 7196.96,3196.13 h60
  text "16" at 5895.05,3046.8 h60
  text "39.37mil (1.000mm)" at 6251.86,3046.8 h60
  text "PTH" at 6912.96,3046.8 h60
  text "Round" at 7196.96,3046.8 h60
  text "3" at 5895.05,2897.46 h60
  text "40.00mil (1.016mm)" at 6251.86,2897.46 h60
  text "PTH" at 6912.96,2897.46 h60
  text "Round" at 7196.96,2897.46 h60
  text "21 Total" at 5895.05,2748.12 h60
  text ".Layer_Name" at 577,-858.49 h60

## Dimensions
0,-400 to 1000,-400 on M2 Board Dimensions
0,0 to 0,2000 on M2 Board Dimensions
0,0 to 2000,0 on M2 Board Dimensions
